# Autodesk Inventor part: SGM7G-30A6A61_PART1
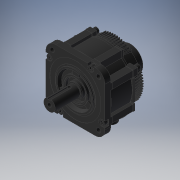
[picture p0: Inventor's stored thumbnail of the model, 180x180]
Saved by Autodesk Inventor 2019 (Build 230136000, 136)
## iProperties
Created: 2019-07
Part Number: SGM7G-30A6A61_PART1
Material: Generic
Catalog Web Link: www.cadenas.de
Description: -
Vendor: YASKAWAUSA
Document SubType Name: Modeling
Designer: psAdmin
Manufacturer: YASKAWAUSA
Mass: 3524.24 g
Surface Area: 2166.03 cm^2
Volume: 3524.24 cm^3
Density: 1 g/cm^3
Appearance: PSOLRGB-175-175-175
Category: PARTsolutions
Company: YASKAWAUSA
Title: SGM7G-30A6A61_PART1
Author: Cadenas PARTsolutions
Sending System: PARTsolutions
PSOL_IDENT_0: {$CADENAS_DATA/23d-libs/yaskawa_usa/motion/sigma_7_servo_products/rotary_servo_motors/sgm7g.prj},198
PSOL_IDENT_1: {VTYP=3D},{NB=SGM7G-30A6A61_PART1},{LINA=SGM7G-30A6A61_PART1},{NN=SGM7G_PART1},{NOPRJ=TRUE},{DATE=2
PSOL_IDENT_2: 3.05.2022 13:08:23},{GEOMDATE=02.02.2021 08:21:09},{VERSION=},{LINEID=1400},{WBVAR=},{WBNUMERIC=}  {
PSOL_IDENT_3: NB=SGM7G-30A6A61_PART1},{LINA=SGM7G-30A6A61_PART1},{KT=DUMMY},{SHA256=Ki2iMjxjCAhV01RQo1wHrteAobWMX1
PSOL_IDENT_4: 4GeladcQJyvY8=},{INAME=00101__sgm7g_30a6a612estep},{PN=SGM7G-30A6A61},{DESC=S7 MTR 3.0KW 200V BAT-LE
PSOL_IDENT_5: SS ABS KW TP},{SERIES=7G},{RATO=3000},{SV=200},{SE=batteryless 24-bit absolute},{DR=A},{SHE=straight
PSOL_IDENT_6: with key and tap},{OPT=without options}
NB: SGM7G-30A6A61_PART1
NBSYN: $PN._PART1
LINA: SGM7G-30A6A61_PART1
CATALOG: Yaskawa
PN: SGM7G-30A6A61
DESC: S7 MTR 3.0KW 200V BAT-LESS ABS KW TP
SERIES: 7G
RATO: 3000
SV: 200
SE: batteryless 24-bit absolute
DR: A
SHE: straight with key and tap
OPT: without options
SUPPLIER: YASKAWAUSA
ARTICLENO: SGM7G-30A6A61_PART1
BOMINFO: SGM7G-30A6A61_PART1
CREATOR: CADENAS GmbH
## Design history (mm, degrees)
feature "NONE"
body "Solid1"
